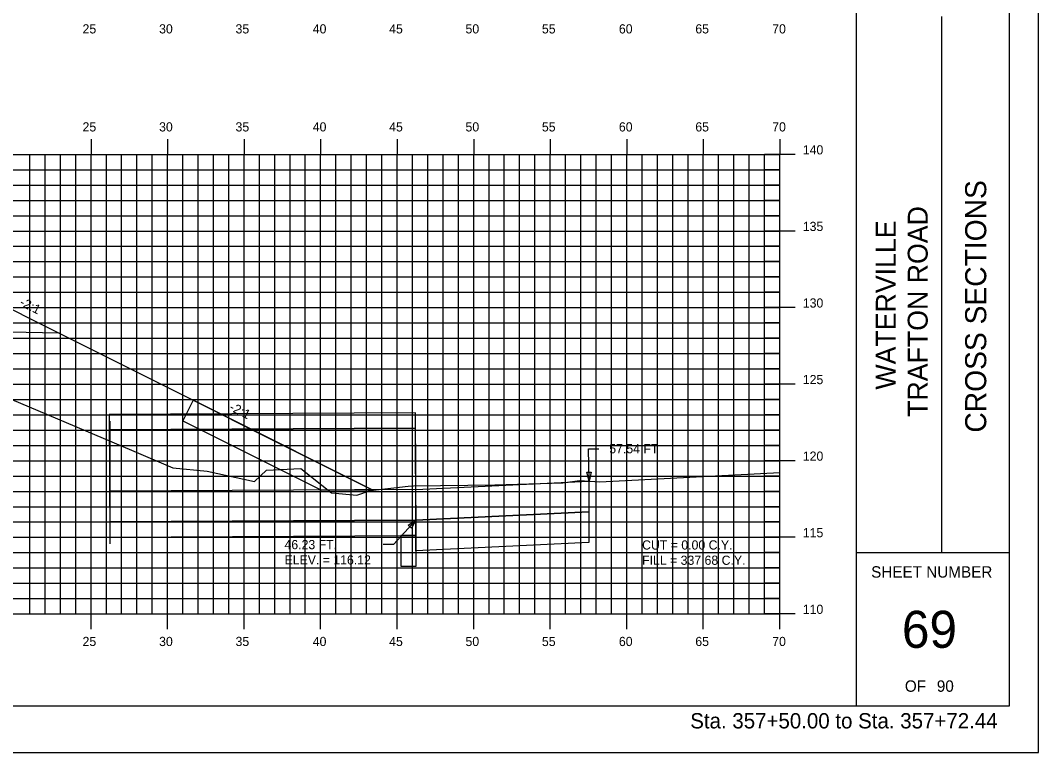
# Model space of a CAD drawing. Extents: x 1145859 to 1146029, y 608981 to 609091.
# Drawn here: x 1145962.8 to 1146029.3, y 608981.3 to 609029.1 of the extents above; entities that cross this region are included whole.
import ezdxf

# ---------------------------------------------------------------- set-up
doc = ezdxf.new("R2010")
doc.units = 0
for name, color, linetype in [('ANNOTATION', 7, 'Continuous'), ('BORDER', 7, 'Continuous'), ('D_Drainage_Culvert', 7, 'Continuous'), ('D_Roadway_SlopeLines', 7, 'Continuous'), ('D_Roadway_SubGrade', 7, 'Continuous'), ('D_Text_Standard', 7, 'Continuous'), ('H_V ANNOTATION', 7, 'Continuous'), ('HIGHWAY_TITLE', 7, 'Continuous'), ('MAJOR', 7, 'Continuous'), ('MINOR', 7, 'Continuous'), ('PATTERNING', 7, 'Continuous'), ('PLOT BOUNDARY', 7, 'Continuous'), ('S_Roadway_Centerline', 7, 'Continuous')]:
    doc.layers.add(name, color=color, linetype=linetype)

msp = doc.modelspace()

# ---------------------------------------------------------------- linework, layer by layer
msp.add_lwpolyline([(1145905.966, 609002.56), (1145916.94, 609007.658), (1145919.092, 609008.658), (1145924.401, 609011.124), (1145924.402, 609011.124), (1145931.402, 609011.404), (1145942.402, 609011.624), (1145953.402, 609011.404), (1145960.402, 609011.124), (1145965.318, 609008.666), (1145967.318, 609007.666), (1145985.816, 608998.417)])
at = {"layer": 'ANNOTATION'}
msp.add_line((1145968.632, 609002.915), (1145968.632, 608994.915), dxfattribs=at)
at = {"layer": 'BORDER'}
for p, q in [((1146017.402, 608984.335), (1146017.402, 609089.335)), ((1146022.993, 608994.338), (1146022.993, 609029.338)), ((1146017.402, 608994.338), (1146027.402, 608994.338))]:
    msp.add_line(p, q, dxfattribs=at)
msp.add_lwpolyline([(1145867.402, 608984.335), (1146027.402, 608984.335), (1146027.402, 609089.335), (1145867.402, 609089.335)], close=True, dxfattribs=at)
at = {"layer": 'D_Drainage_Culvert'}
for points in [[(1145988.637, 608995.455), (1145988.597, 609003.455), (1145968.597, 609003.355), (1145968.637, 608995.355)], [(1145988.632, 608996.455), (1145988.602, 609002.455), (1145968.602, 609002.355), (1145968.632, 608996.355)], [(1145988.637, 608995.455), (1145987.637, 608995.45), (1145987.647, 608993.45), (1145988.647, 608993.455)]]:
    msp.add_lwpolyline(points, close=True, dxfattribs=at)
at = {"layer": 'D_Roadway_SlopeLines'}
for points in [[(1145965.318, 609008.666), (1145967.318, 609007.666)], [(1145967.318, 609007.666), (1145985.768, 608998.441)]]:
    msp.add_lwpolyline(points, dxfattribs=at)
at = {"layer": 'D_Roadway_SubGrade'}
msp.add_lwpolyline([(1145953.402, 609010.987), (1145953.402, 609011.154), (1145960.402, 609010.874), (1145960.402, 609011.124), (1145960.402, 609011.124), (1145965.318, 609008.666), (1145953.402, 609008.904)], close=True, dxfattribs=at)
at = {"layer": 'D_Text_Standard'}
for points in [[(1145999.942, 608999.001), (1145999.898, 609001.122), (1146000.578, 609001.122)], [(1145988.632, 608996.455), (1145987.163, 608994.86), (1145986.483, 608994.86)]]:
    msp.add_lwpolyline(points, dxfattribs=at)
for points in [[(1145999.942, 608999.001), (1145999.784, 608999.58), (1146000.075, 608999.586)], [(1145988.632, 608996.455), (1145988.344, 608995.928), (1145988.13, 608996.125)]]:
    msp.add_lwpolyline(points, close=True, dxfattribs=at)
at = {"layer": 'MAJOR'}
for p, q in [((1145967.402, 609021.337), (1145967.402, 609020.335)), ((1145972.402, 609021.337), (1145972.402, 609020.335)), ((1145977.402, 609021.337), (1145977.402, 609020.335)), ((1145982.402, 609021.337), (1145982.402, 609020.335)), ((1145987.402, 609021.337), (1145987.402, 609020.335)), ((1145992.402, 609021.337), (1145992.402, 609020.335)), ((1145997.402, 609021.337), (1145997.402, 609020.335)), ((1146002.402, 609021.337), (1146002.402, 609020.335)), ((1146007.402, 609021.337), (1146007.402, 609020.335)), ((1146012.402, 609021.337), (1146012.402, 609020.335)), ((1145872.402, 609020.335), (1146012.402, 609020.335)), ((1145872.402, 609020.335), (1146012.402, 609020.335)), ((1145967.402, 608990.335), (1145967.402, 609020.335)), ((1145972.402, 608990.335), (1145972.402, 609020.335)), ((1145977.402, 608990.335), (1145977.402, 609020.335)), ((1145982.402, 608990.335), (1145982.402, 609020.335)), ((1145987.402, 608990.335), (1145987.402, 609020.335)), ((1145992.402, 608990.335), (1145992.402, 609020.335)), ((1145997.402, 608990.335), (1145997.402, 609020.335)), ((1146002.402, 608990.335), (1146002.402, 609020.335)), ((1146007.402, 608990.335), (1146007.402, 609020.335)), ((1146013.404, 609020.335), (1146011.4, 609020.335)), ((1146012.402, 608990.335), (1146012.402, 609020.335)), ((1146012.402, 608990.335), (1146012.402, 609020.335)), ((1145872.402, 609015.335), (1146012.402, 609015.335)), ((1146013.404, 609015.335), (1146011.4, 609015.335)), ((1145872.402, 609010.335), (1146012.402, 609010.335)), ((1146013.404, 609010.335), (1146011.4, 609010.335)), ((1145872.402, 609005.335), (1146012.402, 609005.335)), ((1146013.404, 609005.335), (1146011.4, 609005.335)), ((1145872.402, 609000.335), (1146012.402, 609000.335)), ((1146013.404, 609000.335), (1146011.4, 609000.335)), ((1145872.402, 608995.335), (1146012.402, 608995.335)), ((1146013.404, 608995.335), (1146011.4, 608995.335)), ((1145872.402, 608990.335), (1146012.402, 608990.335)), ((1145872.402, 608990.335), (1146012.402, 608990.335)), ((1145967.402, 608989.333), (1145967.402, 608990.335)), ((1145972.402, 608989.333), (1145972.402, 608990.335)), ((1145977.402, 608989.333), (1145977.402, 608990.335)), ((1145982.402, 608989.333), (1145982.402, 608990.335)), ((1145987.402, 608989.333), (1145987.402, 608990.335)), ((1145992.402, 608989.333), (1145992.402, 608990.335)), ((1145997.402, 608989.333), (1145997.402, 608990.335)), ((1146002.402, 608989.333), (1146002.402, 608990.335)), ((1146007.402, 608989.333), (1146007.402, 608990.335)), ((1146013.404, 608990.335), (1146011.4, 608990.335)), ((1146012.402, 608989.333), (1146012.402, 608990.335))]:
    msp.add_line(p, q, dxfattribs=at)
at = {"layer": 'MINOR'}
for p, q in [((1145963.402, 608990.335), (1145963.402, 609020.335)), ((1145964.402, 608990.335), (1145964.402, 609020.335)), ((1145965.402, 608990.335), (1145965.402, 609020.335)), ((1145966.402, 608990.335), (1145966.402, 609020.335)), ((1145968.402, 608990.335), (1145968.402, 609020.335)), ((1145969.402, 608990.335), (1145969.402, 609020.335)), ((1145970.402, 608990.335), (1145970.402, 609020.335)), ((1145971.402, 608990.335), (1145971.402, 609020.335)), ((1145973.402, 608990.335), (1145973.402, 609020.335)), ((1145974.402, 608990.335), (1145974.402, 609020.335)), ((1145975.402, 608990.335), (1145975.402, 609020.335)), ((1145976.402, 608990.335), (1145976.402, 609020.335)), ((1145978.402, 608990.335), (1145978.402, 609020.335)), ((1145979.402, 608990.335), (1145979.402, 609020.335)), ((1145980.402, 608990.335), (1145980.402, 609020.335)), ((1145981.402, 608990.335), (1145981.402, 609020.335)), ((1145983.402, 608990.335), (1145983.402, 609020.335)), ((1145984.402, 608990.335), (1145984.402, 609020.335)), ((1145985.402, 608990.335), (1145985.402, 609020.335)), ((1145986.402, 608990.335), (1145986.402, 609020.335)), ((1145988.402, 608990.335), (1145988.402, 609020.335)), ((1145989.402, 608990.335), (1145989.402, 609020.335)), ((1145990.402, 608990.335), (1145990.402, 609020.335)), ((1145991.402, 608990.335), (1145991.402, 609020.335)), ((1145993.402, 608990.335), (1145993.402, 609020.335)), ((1145994.402, 608990.335), (1145994.402, 609020.335)), ((1145995.402, 608990.335), (1145995.402, 609020.335)), ((1145996.402, 608990.335), (1145996.402, 609020.335)), ((1145998.402, 608990.335), (1145998.402, 609020.335)), ((1145999.402, 608990.335), (1145999.402, 609020.335)), ((1146000.402, 608990.335), (1146000.402, 609020.335)), ((1146001.402, 608990.335), (1146001.402, 609020.335)), ((1146003.402, 608990.335), (1146003.402, 609020.335)), ((1146004.402, 608990.335), (1146004.402, 609020.335)), ((1146005.402, 608990.335), (1146005.402, 609020.335)), ((1146006.402, 608990.335), (1146006.402, 609020.335)), ((1146008.402, 608990.335), (1146008.402, 609020.335)), ((1146009.402, 608990.335), (1146009.402, 609020.335)), ((1146010.402, 608990.335), (1146010.402, 609020.335)), ((1146011.402, 608990.335), (1146011.402, 609020.335)), ((1145872.402, 609019.335), (1146012.402, 609019.335)), ((1146012.402, 609019.335), (1146011.4, 609019.335)), ((1145872.402, 609018.335), (1146012.402, 609018.335)), ((1146012.402, 609018.335), (1146011.4, 609018.335)), ((1145872.402, 609017.335), (1146012.402, 609017.335)), ((1146012.402, 609017.335), (1146011.4, 609017.335)), ((1145872.402, 609016.335), (1146012.402, 609016.335)), ((1146012.402, 609016.335), (1146011.4, 609016.335)), ((1145872.402, 609014.335), (1146012.402, 609014.335)), ((1146012.402, 609014.335), (1146011.4, 609014.335)), ((1145872.402, 609013.335), (1146012.402, 609013.335)), ((1146012.402, 609013.335), (1146011.4, 609013.335)), ((1145872.402, 609012.335), (1146012.402, 609012.335)), ((1146012.402, 609012.335), (1146011.4, 609012.335)), ((1145872.402, 609011.335), (1146012.402, 609011.335)), ((1146012.402, 609011.335), (1146011.4, 609011.335)), ((1145872.402, 609009.335), (1146012.402, 609009.335)), ((1146012.402, 609009.335), (1146011.4, 609009.335)), ((1145872.402, 609008.335), (1146012.402, 609008.335)), ((1146012.402, 609008.335), (1146011.4, 609008.335)), ((1145872.402, 609007.335), (1146012.402, 609007.335)), ((1146012.402, 609007.335), (1146011.4, 609007.335)), ((1145872.402, 609006.335), (1146012.402, 609006.335)), ((1146012.402, 609006.335), (1146011.4, 609006.335)), ((1145872.402, 609004.335), (1146012.402, 609004.335)), ((1146012.402, 609004.335), (1146011.4, 609004.335)), ((1145872.402, 609003.335), (1146012.402, 609003.335)), ((1146012.402, 609003.335), (1146011.4, 609003.335)), ((1145872.402, 609002.335), (1146012.402, 609002.335)), ((1146012.402, 609002.335), (1146011.4, 609002.335)), ((1145872.402, 609001.335), (1146012.402, 609001.335)), ((1146012.402, 609001.335), (1146011.4, 609001.335)), ((1145872.402, 608999.335), (1146012.402, 608999.335)), ((1146012.402, 608999.335), (1146011.4, 608999.335)), ((1145872.402, 608998.335), (1146012.402, 608998.335)), ((1146012.402, 608998.335), (1146011.4, 608998.335)), ((1145872.402, 608997.335), (1146012.402, 608997.335)), ((1146012.402, 608997.335), (1146011.4, 608997.335)), ((1145872.402, 608996.335), (1146012.402, 608996.335)), ((1146012.402, 608996.335), (1146011.4, 608996.335)), ((1145872.402, 608994.335), (1146012.402, 608994.335)), ((1146012.402, 608994.335), (1146011.4, 608994.335)), ((1145872.402, 608993.335), (1146012.402, 608993.335)), ((1146012.402, 608993.335), (1146011.4, 608993.335)), ((1145872.402, 608992.335), (1146012.402, 608992.335)), ((1146012.402, 608992.335), (1146011.4, 608992.335)), ((1145872.402, 608991.335), (1146012.402, 608991.335)), ((1146012.402, 608991.335), (1146011.4, 608991.335))]:
    msp.add_line(p, q, dxfattribs=at)
at = {"layer": 'PATTERNING'}
for p, q in [((1145975.867, 609003.391), (1145974.078, 609004.286)), ((1145988.602, 609002.455), (1145988.597, 609003.455)), ((1145968.602, 609002.355), (1145988.602, 609002.455)), ((1145988.632, 608996.455), (1145968.632, 608996.355)), ((1145968.632, 608996.355), (1145968.637, 608995.355))]:
    msp.add_line(p, q, dxfattribs=at)
for points in [[(1145985.768, 608998.441), (1145975.867, 609003.391), (1145974.078, 609004.286), (1145973.408, 609002.944), (1145982.448, 608998.424)], [(1145988.632, 608996.455), (1145988.622, 608998.455), (1145968.622, 608998.355), (1145968.632, 608996.355)], [(1145988.622, 608998.455), (1145999.932, 608999.001), (1145999.932, 608997.001), (1145988.622, 608996.455)], [(1145988.622, 608996.455), (1145999.932, 608997.001), (1145999.932, 608995.001), (1145988.622, 608994.455)]]:
    msp.add_lwpolyline(points, close=True, dxfattribs=at)
for points in [[(1145988.597, 609003.455), (1145968.597, 609003.355), (1145968.602, 609002.355)], [(1145988.632, 608995.915), (1145988.632, 608996.455), (1145968.629, 608996.355)], [(1145968.637, 608995.355), (1145988.637, 608995.455), (1145988.632, 608996.455)]]:
    msp.add_lwpolyline(points, dxfattribs=at)
at = {"layer": 'PLOT BOUNDARY'}
msp.add_lwpolyline([(1145859.308, 608981.276), (1146029.308, 608981.276), (1146029.308, 609091.276), (1145859.308, 609091.276)], close=True, dxfattribs=at)
at = {"layer": 'S_Roadway_Centerline'}
msp.add_lwpolyline([(1145960.928, 609004.871), (1145970.05, 609001.035), (1145972.737, 608999.865), (1145974.989, 608999.653), (1145978.087, 608998.971), (1145978.869, 608999.723), (1145981.101, 608999.823), (1145983.112, 608998.242), (1145984.76, 608998.078), (1145985.652, 608998.399), (1145988.114, 608998.667), (1145988.471, 608998.701), (1145993.779, 608998.758), (1145998.232, 608998.896), (1145999.31, 608999.034), (1146000.634, 608998.965), (1146012.402, 608999.562)], dxfattribs=at)

# ---------------------------------------------------------------- texts
at = {"layer": 'ANNOTATION'}
for rotation, p in [(333.4354, (1145962.683, 609010.501)), (333.43495, (1145976.39, 609003.648))]:
    msp.add_text('-2:1', height=0.6, rotation=rotation, dxfattribs=at).set_placement(p)
at = {"layer": 'BORDER'}
msp.add_text('CROSS SECTIONS', height=1.37787, rotation=90, dxfattribs=at).set_placement((1146025.886, 609002.172))
for s, height, p in [('SHEET NUMBER', 0.74527, (1146018.367, 608992.701)), ('69', 2.4194, (1146020.377, 608988.118)), ('OF', 0.7453, (1146020.569, 608985.248)), ('90', 0.7453, (1146022.658, 608985.248))]:
    msp.add_text(s, height=height, dxfattribs=at).set_placement(p)
at = {"layer": 'D_Text_Standard'}
for s, p in [('57.54 FT', (1146001.258, 609000.822)), ('46.23 FT.', (1145980.042, 608994.56)), ('CUT = 0.00 C.Y.', (1146003.402, 608994.535)), ('ELEV. = 116.12', (1145980.042, 608993.56)), ('FILL = 337.68 C.Y.', (1146003.402, 608993.539))]:
    msp.add_text(s, height=0.6, dxfattribs=at).set_placement(p)
at = {"layer": 'H_V ANNOTATION'}
for s, height, p in [('25', 0.6, (1145966.848, 609028.235)), ('30', 0.6, (1145971.85, 609028.235)), ('35', 0.6, (1145976.842, 609028.235)), ('40', 0.6, (1145981.888, 609028.235)), ('45', 0.6, (1145986.88, 609028.235)), ('50', 0.6, (1145991.866, 609028.235)), ('55', 0.6, (1145996.858, 609028.235)), ('60', 0.6, (1146001.888, 609028.235)), ('65', 0.6, (1146006.88, 609028.235)), ('70', 0.6, (1146011.904, 609028.235)), ('25', 0.6, (1145966.848, 609021.835)), ('30', 0.6, (1145971.85, 609021.835)), ('35', 0.6, (1145976.842, 609021.835)), ('40', 0.6, (1145981.888, 609021.835)), ('45', 0.6, (1145986.88, 609021.835)), ('50', 0.6, (1145991.866, 609021.835)), ('55', 0.6, (1145996.858, 609021.835)), ('60', 0.6, (1146001.888, 609021.835)), ('65', 0.6, (1146006.88, 609021.835)), ('70', 0.6, (1146011.904, 609021.835)), ('140', 0.6, (1146013.902, 609020.335)), ('135', 0.6, (1146013.902, 609015.335)), ('130', 0.6, (1146013.902, 609010.335)), ('125', 0.6, (1146013.902, 609005.335)), ('120', 0.6, (1146013.902, 609000.335)), ('115', 0.6, (1146013.902, 608995.335)), ('110', 0.6, (1146013.902, 608990.335)), ('25', 0.6, (1145966.848, 608988.235)), ('30', 0.6, (1145971.85, 608988.235)), ('35', 0.6, (1145976.842, 608988.235)), ('40', 0.6, (1145981.888, 608988.235)), ('45', 0.6, (1145986.88, 608988.235)), ('50', 0.6, (1145991.866, 608988.235)), ('55', 0.6, (1145996.858, 608988.235)), ('60', 0.6, (1146001.888, 608988.235)), ('65', 0.6, (1146006.88, 608988.235)), ('70', 0.6, (1146011.904, 608988.235)), ('Sta. 357+50.00 to Sta. 357+72.44', 1.0002, (1146006.548, 608982.855))]:
    msp.add_text(s, height=height, dxfattribs=at).set_placement(p)
at = {"layer": 'HIGHWAY_TITLE'}
for s, height, p in [('TRAFTON ROAD', 1.30428, (1146022.061, 609003.201)), ('WATERVILLE', 1.3043, (1146019.974, 609004.98))]:
    msp.add_text(s, height=height, rotation=90, dxfattribs=at).set_placement(p)

doc.saveas('drawing.dxf')
